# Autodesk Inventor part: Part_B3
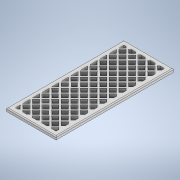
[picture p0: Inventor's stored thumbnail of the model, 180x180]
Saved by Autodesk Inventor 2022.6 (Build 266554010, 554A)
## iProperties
Created: 2025-05
Part Number: Part_B3
Material: Generic
Document SubType Name: Modeling
Designer: khinm
Density: 1 g/cm^3
Appearance: Default
Author: khinm
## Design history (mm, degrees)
sketch "Sketch1"
  geometry: L1 (27.4, -64.9)-(-27.4, -64.9); L2 (-27.4, -64.9)-(-27.4, 64.9); L3 (-27.4, 64.9)-(27.4, 64.9); L4 (27.4, 64.9)-(27.4, -64.9); 3 further points
  constraints: 8 end point, 2 midpoint, 2 parallel, 1 horizontal, 1 horizontal alignment, 1 perpendicular, 1 vertical alignment
  dimensions: "d0" = 54.8 distance of L2.end L3.end; "d1" = 129.8 distance between parallel lines of L3 L1
extrude "Extrusion1" new body sketch "Sketch1" stored distance "d2" = 3.48; taper "d3" = 0 deg
sketch "Sketch2"
  geometry: L1 (22.4, 59.9)-(-22.4, 59.9); L2 (-22.4, -59.9)-(22.4, -59.9); L3 (-27.4, -64.9)-(27.4, -64.9) reference; L4 (-27.4, 64.9)-(-27.4, -64.9) reference; L5 (-18.964, 58.336)-(-22.4, 54.9); L6 (21.899, -59.9)-(22.4, -59.399); L7 (21.899, 59.9)-(22.4, 59.399); L8 (-18.964, -58.336)-(-22.4, -54.9); L9 (16.392, 58.336)-(19.927, 54.801); L10 (21.695, 53.033)-(22.4, 52.328); L11 (19.927, 51.265)-(22.4, 48.792); L12 (22.4, 53.738)-(21.695, 53.033); L13 (17.955, 59.9)-(16.392, 58.336); L14 (11.292, 59.9)-(12.856, 58.336); L15 (14.624, 56.569)-(18.159, 53.033); L16 (12.856, 58.336)-(9.321, 54.801); L17 (5.785, 58.336)-(9.321, 54.801); L18 (14.624, 56.569)-(11.088, 53.033); L19 (11.088, 53.033)-(14.624, 49.497); L20 (9.321, 51.265)-(12.856, 47.73); L21 (19.927, 51.265)-(16.392, 47.73); L22 (16.392, 47.73)-(19.927, 44.194); L23 (21.695, 42.426)-(22.4, 41.721); L24 (14.624, 45.962)-(18.159, 42.426); L25 (19.927, 40.659)-(22.4, 38.186); L26 (22.4, 46.667)-(19.927, 44.194); L27 (22.4, 43.131)-(21.695, 42.426); L28 (19.927, 40.659)-(16.392, 37.123); L29 (18.159, 42.426)-(14.624, 38.891); L30 (14.624, 45.962)-(11.088, 42.426); L31 (11.088, 42.426)-(14.624, 38.891); L32 (12.856, 37.123)-(9.321, 40.659); L33 (12.856, 47.73)-(9.321, 44.194); L34 (5.785, 47.73)-(9.321, 44.194); L35 (9.321, 51.265)-(5.785, 47.73); L36 (7.553, 42.426)-(4.017, 45.962); L37 (7.553, 53.033)-(4.017, 49.497); L38 (16.392, 37.123)-(19.927, 33.588); L39 (21.695, 31.82)-(22.4, 31.115); L40 (22.4, 27.579)-(19.927, 30.052); L41 (18.159, 31.82)-(14.624, 35.355); L42 (22.4, 32.525)-(21.695, 31.82); L43 (22.4, 36.06)-(19.927, 33.588); L44 (22.4, 20.508)-(21.695, 21.213); L45 (22.4, 16.973)-(19.927, 19.445); L46 (22.4, 21.918)-(21.695, 21.213); L47 (22.4, 25.454)-(19.927, 22.981); L48 (19.927, 30.052)-(16.392, 26.517); L49 (19.927, 22.981)-(16.392, 26.517); L50 (18.159, 21.213)-(14.624, 24.749); L51 (18.159, 31.82)-(14.624, 28.284); L52 (14.624, 35.355)-(11.088, 31.82); L53 (12.856, 37.123)-(9.321, 33.588); L54 (9.321, 40.659)-(5.785, 37.123); L55 (7.553, 42.426)-(4.017, 38.891); L56 (14.624, 28.284)-(11.088, 31.82); L57 (12.856, 26.517)-(9.321, 30.052); L58 (9.321, 22.981)-(5.785, 26.517); L59 (7.553, 21.213)-(4.017, 24.749); L60 (14.624, 17.678)-(11.088, 21.213); L61 (12.856, 15.91)-(9.321, 19.445); L62 (9.321, 12.374)-(5.785, 15.91); L63 (7.553, 10.607)-(4.017, 14.142); L64 (22.4, 9.902)-(21.695, 10.607)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; 49 further points
  constraints: 1503 parallel, 834 end point, 11 point on line, 2 horizontal, 1 horizontal alignment, 1 midpoint, 1 vertical alignment, 45 other
  dimensions: "d4" = 5 distance between parallel lines of L3 L2; "d5" = 5 dimension on L4; "d6" = 5 distance of L5.end L1.end; "d44" = 1.87262 distance of L1.end L78.end
extrude "Extrusion2" cut sketch "Sketch2" stored distance "d45" = 3.48; taper "d46" = 0 deg
chamfer "Chamfer1" distance "d47" = 0.4; stored, may be unused: second distance "d48" = 2, angle "d49" = 45 deg
fillet "Fillet1" dims "d50" = 1
body "Solid1"
other parameters: "d4" = 5, "d5" = 5, "d6" = 5, "d8" = 2.5, "d9" = 5, "d10" = 2.5, "d11" = 5, "d12" = 2.5, "d13" = 5, "d14" = 2.5, "d15" = 5, "d16" = 2.5, "d17" = 5, "d18" = 2.5, "d19" = 5, "d20" = 2.5, "d21" = 5, "d22" = 2.5, "d23" = 5, "d24" = 2.5, "d25" = 5, "d26" = 2.5, "d27" = 5, "d28" = 2.5, "d29" = 5, "d30" = 2.5, "d32" = 2.5, "d33" = 5, "d34" = 2.5, "d35" = 5, "d36" = 2.5, "d37" = 5, "d38" = 5, "d39" = 5, "d40" = 5, "d41" = 2.5, "d42" = 2.5, "d43" = 5, "d44" = 1.87262
